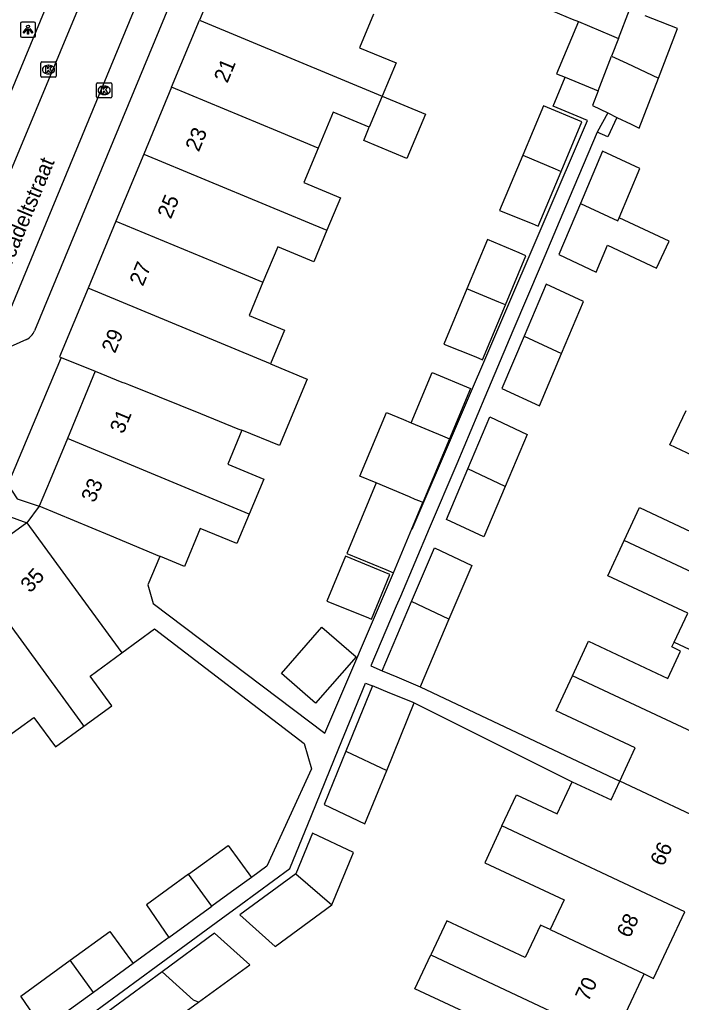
# Model space of a CAD drawing. Extents: x 159822 to 160765, y 380693 to 381634.
# Drawn here: x 160051.4 to 160094.7, y 381310.6 to 381374.9 of the extents above; entities that cross this region are included whole.
import ezdxf

# ---------------------------------------------------------------- set-up
doc = ezdxf.new("R2010")
doc.units = 0
for name, color, linetype in [('IMGEO_Hek', 7, 'Continuous'), ('IMGEO_Kolk', 7, 'Continuous'), ('IMGEO_Lichtpunt', 7, 'Continuous'), ('IMGEO_Openbare_ruimte_label', 7, 'Continuous'), ('IMGEO_Pand', 7, 'Continuous'), ('IMGEO_Pand_nummerreeks', 7, 'Continuous'), ('IMGEO_Rijbaan_lokaal_open', 7, 'Continuous'), ('IMGEO_Voetpad_open', 7, 'Continuous')]:
    doc.layers.add(name, color=color, linetype=linetype)

msp = doc.modelspace()

# ---------------------------------------------------------------- linework, layer by layer
at = {"layer": 'IMGEO_Hek'}
msp.add_lwpolyline([(160089.885, 381368.838), (160089.197, 381367.59)], dxfattribs=at)
at = {"layer": 'IMGEO_Kolk'}
for p, q in [((160052.847, 381372.179), (160053.699, 381372.179)), ((160052.772, 381371.253), (160052.772, 381372.105)), ((160053.26, 381371.959), (160053.285, 381371.959)), ((160053.773, 381372.105), (160053.773, 381371.253)), ((160053.699, 381371.179), (160052.847, 381371.179)), ((160053.283, 381371.399), (160053.258, 381371.399)), ((160056.415, 381369.896), (160056.415, 381370.748)), ((160056.49, 381370.822), (160057.342, 381370.822)), ((160056.903, 381370.602), (160056.928, 381370.602)), ((160057.416, 381370.748), (160057.416, 381369.896)), ((160057.342, 381369.822), (160056.49, 381369.822)), ((160056.926, 381370.042), (160056.901, 381370.042))]:
    msp.add_line(p, q, dxfattribs=at)
for points in [[(160052.847, 381372.179), (160053.699, 381372.179)], [(160052.772, 381371.253), (160052.772, 381372.105)], [(160053.093, 381371.879), (160053.216, 381371.879), (160053.216, 381371.728), (160053.346, 381371.879), (160053.51, 381371.879), (160053.364, 381371.728), (160053.517, 381371.479), (160053.365, 381371.479), (160053.28, 381371.643), (160053.216, 381371.576), (160053.216, 381371.479), (160053.093, 381371.479), (160053.093, 381371.879)], [(160053.773, 381372.105), (160053.773, 381371.253)], [(160053.699, 381371.179), (160052.847, 381371.179)], [(160056.415, 381369.896), (160056.415, 381370.748)], [(160056.49, 381370.822), (160057.342, 381370.822)], [(160056.736, 381370.522), (160056.859, 381370.522), (160056.859, 381370.371), (160056.989, 381370.522), (160057.153, 381370.522), (160057.007, 381370.371), (160057.16, 381370.122), (160057.008, 381370.122), (160056.923, 381370.286), (160056.859, 381370.219), (160056.859, 381370.122), (160056.736, 381370.122), (160056.736, 381370.522)], [(160057.416, 381370.748), (160057.416, 381369.896)], [(160057.342, 381369.822), (160056.49, 381369.822)]]:
    msp.add_lwpolyline(points, dxfattribs=at)
for centre, start, end in [((160052.849, 381372.103), 91.55205, 178.44795), ((160052.849, 381372.103), 91.55205, 178.44795), ((160053.697, 381372.103), 1.55205, 88.44795), ((160053.697, 381372.103), 1.55205, 88.44795), ((160052.849, 381371.255), 181.55205, 268.44795), ((160052.849, 381371.255), 181.55205, 268.44795), ((160053.697, 381371.255), 271.55205, 358.44795), ((160053.697, 381371.255), 271.55205, 358.44795), ((160056.492, 381370.746), 91.55205, 178.44795), ((160056.492, 381370.746), 91.55205, 178.44795), ((160057.34, 381370.746), 1.55205, 88.44795), ((160057.34, 381370.746), 1.55205, 88.44795), ((160056.492, 381369.898), 181.55205, 268.44795), ((160056.492, 381369.898), 181.55205, 268.44795), ((160057.34, 381369.898), 271.55205, 358.44795), ((160057.34, 381369.898), 271.55205, 358.44795)]:
    msp.add_arc(centre, 0.0765, start, end, dxfattribs=at)
for centre, major_axis, ratio, start_param, end_param in [((160053.259, 381371.679), (-0.387, 0.002), 0.722429, 4.712389, 7.853982), ((160053.284, 381371.679), (-0.39, 0.002), 0.717154, 1.570796, 4.712389), ((160056.902, 381370.322), (-0.387, 0.002), 0.722429, 4.712389, 7.853982), ((160056.927, 381370.322), (-0.39, 0.002), 0.717154, 1.570796, 4.712389)]:
    msp.add_ellipse(centre, major_axis=major_axis, ratio=ratio, start_param=start_param, end_param=end_param, dxfattribs=at)
at = {"layer": 'IMGEO_Lichtpunt'}
for p, q in [((160051.433, 381374.699), (160051.433, 381373.892)), ((160051.433, 381374.699), (160051.433, 381373.892)), ((160052.335, 381374.794), (160051.527, 381374.794)), ((160052.335, 381374.794), (160051.527, 381374.794)), ((160052.429, 381373.892), (160052.429, 381374.699)), ((160052.429, 381373.892), (160052.429, 381374.699)), ((160051.527, 381373.798), (160052.335, 381373.798)), ((160051.527, 381373.798), (160052.335, 381373.798))]:
    msp.add_line(p, q, dxfattribs=at)
for points in [[(160051.807, 381374.363), (160051.846, 381374.335), (160051.658, 381374.073), (160051.62, 381374.1), (160051.807, 381374.363)], [(160051.909, 381374.315), (160051.956, 381374.315), (160051.956, 381373.993), (160051.909, 381373.993), (160051.909, 381374.315)], [(160052.019, 381374.335), (160052.057, 381374.362), (160052.244, 381374.1), (160052.205, 381374.072), (160052.019, 381374.335)]]:
    msp.add_lwpolyline(points, dxfattribs=at)
msp.add_circle((160051.932, 381374.497), 0.0994, dxfattribs=at)
for centre, start, end in [((160051.527, 381374.699), 90, 180), ((160051.527, 381374.699), 90, 180), ((160052.335, 381374.699), 0, 90), ((160052.335, 381374.699), 0, 90), ((160051.527, 381373.892), 180, 270), ((160051.527, 381373.892), 180, 270), ((160052.335, 381373.892), 270, 0), ((160052.335, 381373.892), 270, 360)]:
    msp.add_arc(centre, 0.0946, start, end, dxfattribs=at)
at = {"layer": 'IMGEO_Pand'}
for points in [[(160092.229, 381377.996), (160092.237, 381378.016), (160087.669, 381379.922), (160087.641, 381379.855), (160086.351, 381376.766), (160083.538, 381377.944), (160083.085, 381376.861), (160085.899, 381375.682), (160087.557, 381374.988), (160087.965, 381374.817)], [(160064.978, 381379.288), (160063.157, 381374.906)], [(160090.582, 381373.722), (160091.3, 381375.585)], [(160061.335, 381370.524), (160063.157, 381374.906)], [(160063.157, 381374.906), (160075.113, 381369.936)], [(160074.55, 381375.31), (160073.637, 381373.113), (160076.022, 381372.122), (160075.113, 381369.936)], [(160087.965, 381374.817), (160086.536, 381371.395), (160087.085, 381371.173)], [(160087.965, 381374.817), (160090.115, 381373.917), (160090.582, 381373.722)], [(160093.204, 381371.123), (160094.455, 381374.37), (160092.83, 381374.996), (160092.331, 381375.188)], [(160090.582, 381373.722), (160090.134, 381372.56)], [(160089.261, 381370.291), (160090.134, 381372.56)], [(160090.134, 381372.56), (160091.137, 381372.091), (160093.204, 381371.123)], [(160087.085, 381371.173), (160089.261, 381370.291)], [(160090.484, 381368.551), (160091.415, 381368.104), (160091.944, 381367.85), (160093.204, 381371.123)], [(160061.335, 381370.524), (160059.513, 381366.141)], [(160070.931, 381366.535), (160068.27, 381367.641), (160061.335, 381370.524)], [(160089.261, 381370.291), (160088.886, 381369.317), (160089.885, 381368.838), (160090.484, 381368.551)], [(160075.113, 381369.936), (160077.941, 381368.76), (160076.739, 381365.868), (160073.91, 381367.044), (160074.27, 381367.907)], [(160075.113, 381369.936), (160074.27, 381367.907)], [(160086.832, 381365.017), (160088.185, 381368.261), (160085.666, 381369.312), (160084.313, 381366.071)], [(160074.27, 381367.907), (160071.909, 381368.888), (160070.931, 381366.535)], [(160070.931, 381366.535), (160069.995, 381364.284), (160072.378, 381363.293), (160071.492, 381361.162)], [(160090.625, 381361.981), (160091.989, 381365.198), (160089.537, 381366.329), (160088.089, 381362.914)], [(160059.513, 381366.141), (160057.691, 381361.758)], [(160059.513, 381366.141), (160071.492, 381361.162)], [(160084.313, 381366.071), (160082.805, 381362.458), (160084.94, 381361.594), (160085.336, 381361.434), (160086.832, 381365.017)], [(160084.313, 381366.071), (160086.438, 381365.182), (160086.832, 381365.017)], [(160088.089, 381362.914), (160086.668, 381359.564), (160089.115, 381358.418), (160089.861, 381360.179), (160093.077, 381358.674), (160093.906, 381360.446), (160090.625, 381361.981)], [(160088.089, 381362.914), (160090.535, 381361.769), (160090.625, 381361.981)], [(160057.691, 381361.758), (160055.87, 381357.375)], [(160057.691, 381361.758), (160064.631, 381358.873), (160067.312, 381357.759)], [(160071.492, 381361.162), (160070.636, 381359.103), (160068.278, 381360.084), (160067.312, 381357.759)], [(160083.18, 381356.269), (160084.526, 381359.493), (160084.088, 381359.676), (160082.006, 381360.544), (160080.661, 381357.323)], [(160055.87, 381357.375), (160053.998, 381352.872), (160054.093, 381352.833)], [(160067.813, 381352.411), (160055.87, 381357.375)], [(160067.312, 381357.759), (160066.408, 381355.585), (160068.731, 381354.619), (160067.813, 381352.411)], [(160080.661, 381357.323), (160079.152, 381353.71), (160081.244, 381352.863), (160081.684, 381352.685), (160083.18, 381356.269)], [(160083.18, 381356.269), (160082.742, 381356.452), (160080.661, 381357.323)], [(160086.853, 381353.08), (160088.3, 381356.495), (160085.853, 381357.641), (160084.405, 381354.225)], [(160084.405, 381354.225), (160082.957, 381350.81), (160085.405, 381349.663), (160086.853, 381353.08)], [(160084.405, 381354.225), (160086.853, 381353.08)], [(160054.093, 381352.833), (160056.337, 381351.925)], [(160067.813, 381352.411), (160070.205, 381351.417), (160068.401, 381347.077), (160065.923, 381348.068)], [(160056.337, 381351.925), (160054.509, 381347.527)], [(160056.337, 381351.925), (160058.074, 381351.223), (160058.285, 381351.141), (160058.5, 381351.057), (160060.507, 381350.249), (160063.232, 381349.152), (160065.677, 381348.167), (160065.923, 381348.068)], [(160077.003, 381348.562), (160078.378, 381351.856), (160080.899, 381350.804), (160079.523, 381347.506)], [(160074.718, 381344.615), (160073.655, 381345.061), (160075.397, 381349.235), (160076.5, 381348.773), (160077.003, 381348.562)], [(160098.19, 381342.662), (160099.134, 381344.677), (160093.952, 381347.102), (160095.007, 381349.357)], [(160077.003, 381348.562), (160079.058, 381347.701), (160079.523, 381347.506)], [(160080.721, 381345.537), (160082.161, 381348.934), (160084.61, 381347.787), (160083.17, 381344.391)], [(160065.923, 381348.068), (160065.003, 381345.854), (160067.365, 381344.872), (160066.411, 381342.578)], [(160054.509, 381347.527), (160053.375, 381344.8), (160052.664, 381343.089)], [(160066.411, 381342.578), (160054.509, 381347.527)], [(160079.523, 381347.506), (160077.78, 381343.332)], [(160083.17, 381344.391), (160081.767, 381341.079), (160079.319, 381342.229), (160080.721, 381345.537)], [(160083.17, 381344.391), (160080.721, 381345.537)], [(160074.718, 381344.615), (160074.24, 381343.469), (160072.792, 381339.999), (160075.358, 381338.948), (160075.864, 381338.741)], [(160077.78, 381343.332), (160077.572, 381343.419), (160077.276, 381343.543), (160076.907, 381343.698), (160074.718, 381344.615)], [(160077.06, 381341.607), (160077.78, 381343.332)], [(160060.553, 381339.81), (160057.281, 381341.17), (160052.664, 381343.089)], [(160066.411, 381342.578), (160065.608, 381340.646), (160063.212, 381341.642), (160062.171, 381339.137), (160060.598, 381339.791), (160060.553, 381339.81)], [(160090.952, 381340.842), (160091.963, 381343.002), (160097.201, 381340.55), (160098.19, 381342.662)], [(160051.849, 381342.011), (160050.798, 381341.244), (160047.948, 381339.164)], [(160051.849, 381342.011), (160054.796, 381337.972), (160058.069, 381333.488)], [(160075.864, 381338.741), (160077.06, 381341.607)], [(160094.231, 381334.201), (160095.116, 381336.091), (160089.876, 381338.544), (160090.952, 381340.842)], [(160103.018, 381335.194), (160090.952, 381340.842)], [(160077.037, 381336.848), (160078.53, 381340.369), (160080.978, 381339.219), (160079.486, 381335.697)], [(160072.718, 381339.822), (160071.492, 381336.885), (160074.063, 381335.845), (160074.406, 381335.706), (160075.627, 381338.631), (160072.718, 381339.822)], [(160055.586, 381328.689), (160055.512, 381328.791), (160047.948, 381339.164)], [(160075.119, 381332.324), (160077.037, 381336.848)], [(160079.486, 381335.697), (160077.037, 381336.848)], [(160079.486, 381335.697), (160077.609, 381331.269)], [(160071.165, 381335.175), (160073.402, 381333.227), (160070.756, 381330.188), (160068.519, 381332.135), (160071.165, 381335.175)], [(160087.572, 381331.993), (160088.629, 381334.249), (160093.815, 381331.821), (160094.652, 381333.61), (160094.08, 381333.878), (160094.231, 381334.201)], [(160094.231, 381334.201), (160101.593, 381330.742)], [(160055.586, 381328.689), (160057.418, 381330.026), (160055.996, 381331.975), (160058.069, 381333.488)], [(160075.119, 381332.324), (160076.068, 381331.922), (160077.609, 381331.269)], [(160090.669, 381325.092), (160091.672, 381327.273), (160086.497, 381329.696), (160087.572, 381331.993)], [(160099.542, 381326.37), (160087.572, 381331.993)], [(160074.477, 381331.327), (160072.736, 381327.051)], [(160077.217, 381330.211), (160075.619, 381330.862), (160074.477, 381331.327)], [(160075.416, 381325.79), (160077.217, 381330.211)], [(160050.169, 381327.896), (160050.263, 381327.767), (160052.323, 381329.27), (160053.733, 381327.337), (160055.586, 381328.689)], [(160072.736, 381327.051), (160071.311, 381323.554), (160073.99, 381322.289), (160075.416, 381325.79)], [(160072.736, 381327.051), (160075.416, 381325.79)], [(160082.954, 381322.167), (160083.906, 381324.2), (160086.568, 381322.954), (160087.547, 381325.044)], [(160087.547, 381325.044), (160090.104, 381323.862), (160090.669, 381325.092)], [(160097.45, 381321.91), (160090.669, 381325.092)], [(160082.954, 381322.167), (160081.825, 381319.755), (160087.031, 381317.317), (160086.121, 381315.373)], [(160094.93, 381316.539), (160082.954, 381322.167)], [(160071.83, 381316.988), (160073.231, 381320.426), (160070.552, 381321.691), (160069.47, 381319.034)], [(160062.436, 381318.999), (160065.024, 381320.886), (160066.554, 381318.788)], [(160062.436, 381318.999), (160059.683, 381316.991), (160061.152, 381314.849)], [(160063.964, 381316.899), (160062.436, 381318.999)], [(160066.554, 381318.788), (160065.259, 381317.844), (160063.964, 381316.899)], [(160069.47, 381319.034), (160065.791, 381316.334), (160068.106, 381314.271), (160071.83, 381316.988)], [(160069.47, 381319.034), (160071.83, 381316.988)], [(160061.152, 381314.849), (160063.964, 381316.899)], [(160092.258, 381312.476), (160092.885, 381312.18), (160094.93, 381316.539)], [(160086.121, 381315.373), (160085.483, 381315.674), (160084.483, 381313.538), (160079.34, 381315.946), (160078.304, 381313.732)], [(160054.69, 381313.365), (160057.278, 381315.252), (160058.808, 381313.154)], [(160063.09, 381310.612), (160066.46, 381313.071), (160064.15, 381315.13), (160060.705, 381312.6)], [(160086.121, 381315.373), (160092.258, 381312.476)], [(160081.462, 381307.071), (160082.405, 381309.085), (160077.257, 381311.496), (160078.304, 381313.732)], [(160078.304, 381313.732), (160090.221, 381308.123)], [(160052.931, 381308.869), (160051.462, 381311.011), (160054.69, 381313.365)], [(160056.218, 381311.266), (160054.69, 381313.365)], [(160058.808, 381313.154), (160056.218, 381311.266)], [(160060.705, 381312.6), (160056.439, 381309.469), (160058.49, 381307.641), (160058.811, 381307.491), (160063.09, 381310.612)], [(160063.09, 381310.612), (160062.765, 381310.764), (160060.705, 381312.6)], [(160090.221, 381308.123), (160092.258, 381312.476)], [(160056.218, 381311.266), (160052.931, 381308.869)]]:
    msp.add_lwpolyline(points, dxfattribs=at)
at = {"layer": 'IMGEO_Rijbaan_lokaal_open'}
for points in [[(160058.74, 381384.186), (160046.049, 381353.712)], [(160049.223, 381352.25), (160061.916, 381382.928)]]:
    msp.add_lwpolyline(points, dxfattribs=at)
at = {"layer": 'IMGEO_Voetpad_open'}
for points in [[(160058.135, 381384.019), (160056.734, 381384.568), (160045.408, 381357.267)], [(160062.221, 381382.345), (160063.606, 381381.776), (160052.353, 381354.57)], [(160077.06, 381341.607), (160077.087, 381341.594), (160088.561, 381368.349), (160087.878, 381368.634), (160086.3, 381369.293), (160087.085, 381371.173)], [(160090.484, 381368.551), (160089.893, 381367.269), (160089.197, 381367.59), (160087.359, 381363.255), (160085.518, 381358.911), (160083.677, 381354.566), (160081.836, 381350.223), (160079.994, 381345.877), (160078.198, 381341.639), (160076.312, 381337.188), (160076.041, 381336.548), (160074.382, 381332.636), (160075.119, 381332.324)], [(160051.83, 381354.015), (160050.324, 381353.327)], [(160054.093, 381352.833), (160050.607, 381344.513), (160051.233, 381343.569), (160052.664, 381343.089)], [(160042.579, 381338.36), (160049.274, 381343.128), (160049.447, 381342.874), (160051.849, 381342.011)], [(160052.664, 381343.089), (160051.849, 381342.011)], [(160060.553, 381339.81), (160059.781, 381337.955), (160060.134, 381336.722), (160071.357, 381328.232), (160075.864, 381338.741)], [(160058.069, 381333.488), (160060.215, 381335.054), (160070.007, 381327.562), (160070.492, 381325.889), (160067.562, 381319.523), (160066.554, 381318.788)], [(160050.389, 381280.071), (160038.546, 381285.838), (160034.21, 381289.545), (160033.816, 381289.258), (160031.367, 381291.706), (160034.717, 381294.165), (160038.984, 381297.296), (160043.25, 381300.426), (160047.516, 381303.556), (160051.783, 381306.687), (160056.049, 381309.817), (160060.315, 381312.948), (160064.581, 381316.078), (160065.864, 381317.019), (160069.076, 381319.376), (160070.485, 381322.835), (160072.288, 381327.261), (160074.02, 381331.513), (160074.477, 381331.327)], [(160077.609, 381331.269), (160090.669, 381325.092)], [(160077.217, 381330.211), (160087.547, 381325.044)], [(160061.152, 381314.849), (160060.677, 381314.503), (160058.808, 381313.154)]]:
    msp.add_lwpolyline(points, dxfattribs=at)
msp.add_arc((160051.427, 381354.919), 0.99, 294.0408, 339.3598, dxfattribs=at)

# ---------------------------------------------------------------- texts
at = {"layer": 'IMGEO_Openbare_ruimte_label'}
msp.add_text('Arcadeltstraat', height=1, rotation=67.411, dxfattribs=at).set_placement((160050.522, 381358.039))
at = {"layer": 'IMGEO_Pand_nummerreeks'}
for s, rotation, p in [('21', 67.42881, (160064.98, 381370.746)), ('23', 67.42881, (160063.108, 381366.244)), ('25', 67.42881, (160061.279, 381361.845)), ('27', 67.42881, (160059.451, 381357.447)), ('29', 67.4314, (160057.623, 381353.05)), ('31', 67.42567, (160058.167, 381347.782)), ('33', 67.42567, (160056.291, 381343.271)), ('35', 48.00372, (160052.083, 381337.37)), ('66', 64.86455, (160093.515, 381319.457)), ('68', 64.86455, (160091.317, 381314.769)), ('70', 64.91612, (160088.602, 381310.607))]:
    msp.add_text(s, height=1, rotation=rotation, dxfattribs=at).set_placement(p)

doc.saveas('drawing.dxf')
